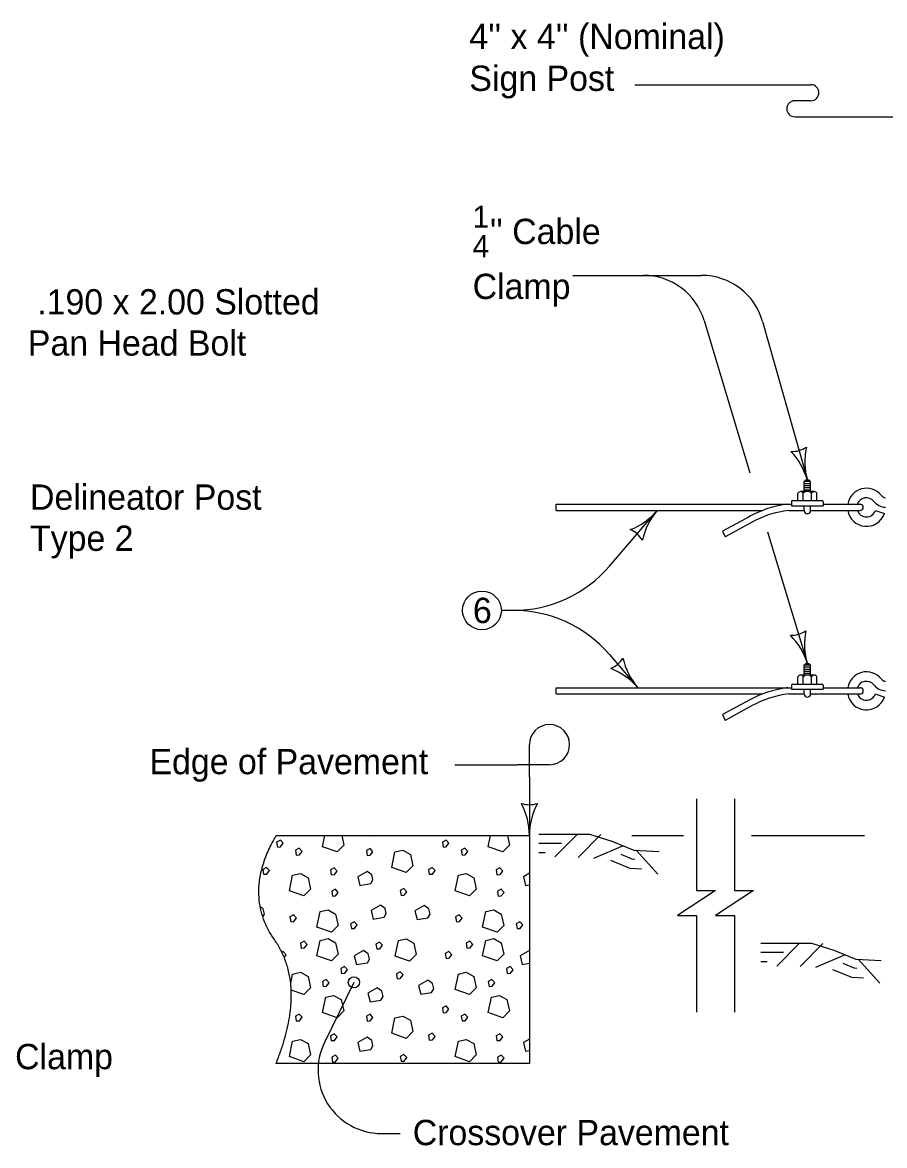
# Model space of a CAD drawing. Extents: x 228 to 3572, y -1307 to 1277.
# Drawn here: x 858 to 1403, y -886 to -176 of the extents above; entities that cross this region are included whole.
import ezdxf

# ---------------------------------------------------------------- set-up
doc = ezdxf.new("R2010")
doc.units = 0
for name, color, linetype in [('dsnStdDimension', 7, 'Continuous'), ('Level 2', 7, 'Continuous'), ('Level 3', 7, 'Continuous')]:
    doc.layers.add(name, color=color, linetype=linetype)

msp = doc.modelspace()

# ---------------------------------------------------------------- linework, layer by layer
at = {"layer": 'dsnStdDimension'}
for p, q in [((1245.31, -215.67), (1356.53, -215.67)), ((1356.53, -225.83), (1346.37, -225.83)), ((1346.37, -235.99), (1428.56, -235.99)), ((1206.22, -336.19), (1287.48, -336.19)), ((1289.05, -364.67), (1318.02, -460.97)), ((1325.97, -365.32), (1354.34, -465.71)), ((1229.26, -520.02), (1259.45, -484.8)), ((1329.22, -498.21), (1354.34, -581.71)), ((1229.26, -575.88), (1247.19, -596.8)), ((1178.7, -653.09), (1178.7, -632.77)), ((1131.52, -645.47), (1171.08, -645.47)), ((1191.4, -645.47), (1171.08, -645.47)), ((1178.7, -653.09), (1178.7, -690.3)), ((1067.85, -783.05), (1049.27, -821.01)), ((1085.2, -878.59), (1096.97, -878.59))]:
    msp.add_line(p, q, dxfattribs=at)
msp.add_circle((1067.85, -783.05), 3.56, dxfattribs=at)
for centre, radius, start, end in [((1356.53, -220.75), 5.08, 270, 90), ((1346.37, -230.91), 5.08, 90, 270), ((1250.74, -376.19), 40, 16.74258, 90), ((1287.48, -376.19), 40, 15.77718, 90), ((1344.49, -430.86), 16.68, 268.04366, 303.51036), ((1395.89, -453.97), 43.18, 167.70452, 195.77701), ((1312.78, -477.45), 43.18, 15.77701, 43.8495), ((1226.67, -456.7), 43.18, 291.32247, 319.39496), ((1292.24, -512.9), 43.18, 139.39496, 167.46744), ((1235.89, -512.29), 16.68, 31.6616, 67.12831), ((1168.52, -467.96), 80, 270, 319.39431), ((1168.52, -627.96), 80, 40.60903, 90), ((1343.91, -547.04), 16.68, 269.00857, 304.47527), ((1312.99, -594.14), 43.18, 16.74192, 44.81441), ((1395.68, -569.27), 43.18, 168.66943, 196.74192), ((1223.62, -569.31), 16.68, 292.86794, 328.33464), ((1279.97, -568.7), 43.18, 192.52881, 220.60129), ((1214.4, -624.9), 43.18, 40.60129, 68.67378), ((1191.4, -632.77), 12.7, 270, 180), ((1178.7, -654.09), 16.68, 252.26665, 287.73335), ((1135.52, -690.3), 43.18, 0, 28.07249), ((1221.88, -690.3), 43.18, 151.92751, 180), ((1085.2, -838.59), 40, 153.92317, 270)]:
    msp.add_arc(centre, radius, start, end, dxfattribs=at)
at = {"layer": 'Level 2'}
for p, q in [((1352.34, -466.54), (1353.17, -465.71)), ((1352.34, -472.86), (1352.34, -466.54)), ((1356, -466.54), (1352.67, -466.54)), ((1356, -467.87), (1352.67, -467.87)), ((1355.5, -465.71), (1353.17, -465.71)), ((1356.34, -466.54), (1355.5, -465.71)), ((1356.34, -472.86), (1356.34, -466.54)), ((1348.34, -478.52), (1348.34, -473.86)), ((1351.67, -472.86), (1350, -472.86)), ((1357, -472.86), (1351.67, -472.86)), ((1351.67, -478.52), (1351.67, -473.86)), ((1356, -469.21), (1352.67, -469.21)), ((1356, -470.54), (1352.67, -470.54)), ((1356, -471.87), (1352.67, -471.87)), ((1358.67, -472.86), (1357, -472.86)), ((1357, -478.52), (1357, -473.86)), ((1360.34, -478.52), (1360.34, -473.86)), ((1195.61, -480.8), (1344.34, -480.8)), ((1195.61, -484.8), (1195.61, -480.8)), ((1344.34, -479.32), (1344.34, -481.8)), ((1344.34, -481.8), (1364.34, -481.8)), ((1345.14, -478.52), (1363.54, -478.52)), ((1352.34, -484.8), (1352.34, -481.8)), ((1356.34, -484.8), (1356.34, -481.8)), ((1364.34, -479.32), (1364.34, -481.8)), ((1364.34, -480.8), (1387.61, -480.8)), ((1195.61, -484.8), (1325.97, -484.8)), ((1317.88, -488.51), (1300.69, -497.81)), ((1342.58, -484.8), (1352.34, -484.8)), ((1356.34, -484.8), (1387.61, -484.8)), ((1397.27, -484.8), (1402.93, -486.79)), ((1319.5, -492.15), (1302.43, -501.49)), ((1300.69, -497.81), (1302.43, -501.49)), ((1168.52, -547.96), (1160.98, -547.96)), ((1352.34, -582.54), (1353.17, -581.71)), ((1355.5, -581.71), (1353.17, -581.71)), ((1356.34, -582.54), (1355.5, -581.71)), ((1351.67, -588.86), (1350, -588.86)), ((1357, -588.86), (1351.67, -588.86)), ((1352.34, -588.86), (1352.34, -582.54)), ((1356, -582.54), (1352.67, -582.54)), ((1356, -583.87), (1352.67, -583.87)), ((1356, -585.21), (1352.67, -585.21)), ((1356, -586.54), (1352.67, -586.54)), ((1356, -587.87), (1352.67, -587.87)), ((1356.34, -588.86), (1356.34, -582.54)), ((1358.67, -588.86), (1357, -588.86)), ((1344.34, -595.32), (1344.34, -597.8)), ((1345.14, -594.52), (1363.54, -594.52)), ((1348.34, -594.52), (1348.34, -589.86)), ((1351.67, -594.52), (1351.67, -589.86)), ((1357, -594.52), (1357, -589.86)), ((1360.34, -594.52), (1360.34, -589.86)), ((1364.34, -595.32), (1364.34, -597.8)), ((1195.61, -596.8), (1344.34, -596.8)), ((1195.61, -600.8), (1195.61, -596.8)), ((1195.61, -600.8), (1325.97, -600.8)), ((1342.58, -600.8), (1352.34, -600.8)), ((1344.34, -597.8), (1364.34, -597.8)), ((1352.34, -600.8), (1352.34, -597.8)), ((1356.34, -600.8), (1356.34, -597.8)), ((1356.34, -600.8), (1387.61, -600.8)), ((1364.34, -596.8), (1387.61, -596.8)), ((1397.27, -600.8), (1402.93, -602.79)), ((1317.88, -604.51), (1300.69, -613.81)), ((1319.5, -608.15), (1302.43, -617.49)), ((1300.69, -613.81), (1302.43, -617.49)), ((1018.7, -690.3), (1178.7, -690.3)), ((1178.7, -690.3), (1178.7, -834.3)), ((1209.09, -689.45), (1194.73, -703.82)), ((1223.83, -689.68), (1209.46, -704.05)), ((1243.43, -690.3), (1275.96, -690.3)), ((1319.05, -690.3), (1390.43, -690.3)), ((1237.99, -696.75), (1219.28, -704.68)), ((1246.23, -699.54), (1259.75, -714.72)), ((1349.34, -758.36), (1334.97, -772.73)), ((1364.07, -758.59), (1349.7, -772.96)), ((1378.23, -765.66), (1359.52, -773.59)), ((1386.48, -768.46), (1399.99, -783.63)), ((1178.7, -834.3), (1018.7, -834.3))]:
    msp.add_line(p, q, dxfattribs=at)
for points in [[(1284.21, -666.96), (1284.21, -724.9), (1296.21, -724.9), (1272.21, -740.9), (1284.21, -740.9), (1284.21, -801.85)], [(1308.21, -666.96), (1308.21, -724.9), (1320.21, -724.9), (1296.21, -740.9), (1308.21, -740.9), (1308.21, -801.85)], [(1060.12, -690.3), (1061.42, -696.26), (1057.22, -700.61), (1048.06, -697.35), (1049.51, -690.3)], [(1077.98, -690.3), (1078.04, -690.52), (1079.4, -690.3)], [(1164.79, -690.3), (1166.09, -696.26), (1161.89, -700.61), (1152.73, -697.35), (1154.18, -690.3)], [(1184.7, -689.45), (1200.7, -689.45), (1216.69, -689.45), (1230.78, -693.83), (1244.69, -699.45), (1260.6, -700.38)], [(1184.7, -695.01), (1198.94, -695.01)], [(1184.7, -700.9), (1188.56, -700.9)], [(1236.38, -702.12), (1243.44, -704.98), (1245.39, -705.09)], [(1229.94, -705.93), (1242.12, -710.86), (1249.57, -711.29)], [(1178.7, -714.13), (1174.94, -716.3)], [(1174.94, -716.3), (1176.34, -721.74), (1178.7, -721.36)], [(1010.28, -741.58), (1011.28, -739.92), (1010.5, -736.65), (1008.61, -735.27)], [(1324.94, -758.36), (1340.94, -758.36), (1356.94, -758.36), (1371.02, -762.74), (1384.93, -768.37), (1400.85, -769.29)], [(1023.89, -767.21), (1025.1, -765.66), (1023.24, -763.64), (1022.37, -764.11)], [(1178.7, -762.9), (1178.67, -762.87), (1172.77, -766.29)], [(1172.77, -766.29), (1174.16, -771.72), (1178.7, -771)], [(1324.94, -763.92), (1339.18, -763.92)], [(1324.94, -769.81), (1328.81, -769.81)], [(1376.62, -771.03), (1383.69, -773.89), (1385.63, -774)], [(1376.62, -771.03), (1383.69, -773.89), (1385.63, -774)], [(1027.93, -783.64), (1029.14, -777.78)], [(1029.14, -777.78), (1034.11, -776.69), (1038.93, -779.34), (1040.48, -786.48), (1036.29, -790.83), (1028.25, -787.97)], [(1370.19, -774.85), (1382.37, -779.77), (1389.81, -780.2)], [(1370.19, -774.85), (1382.37, -779.77), (1389.81, -780.2)], [(1178.7, -818.95), (1174.94, -821.13)], [(1174.94, -821.13), (1176.34, -826.56), (1178.7, -826.19)]]:
    msp.add_lwpolyline(points, dxfattribs=at)
for points in [[(1019.04, -694.4), (1019.51, -697.51), (1021.53, -697.35), (1023.24, -695.17), (1021.37, -693.16)], [(1123.71, -694.4), (1124.18, -697.51), (1126.2, -697.35), (1127.91, -695.17), (1126.04, -693.16)], [(1031.01, -699.52), (1031.47, -702.63), (1033.49, -702.48), (1035.2, -700.3), (1033.34, -698.28)], [(1075.71, -699.68), (1076.18, -702.79), (1078.19, -702.63), (1079.9, -700.46), (1078.04, -698.44)], [(1093.73, -700.61), (1098.7, -699.52), (1103.52, -702.17), (1105.07, -709.31), (1100.88, -713.66), (1091.71, -710.4)], [(1135.67, -699.52), (1136.14, -702.63), (1138.16, -702.48), (1139.87, -700.3), (1138, -698.28)], [(1010.35, -711.64), (1010.81, -714.75), (1012.83, -714.59), (1014.54, -712.42), (1012.68, -710.4)], [(1029.14, -715.37), (1034.11, -714.28), (1038.93, -716.92), (1040.48, -724.07), (1036.29, -728.42), (1027.12, -725.16)], [(1053.03, -711.95), (1053.49, -715.06), (1055.51, -714.9), (1057.22, -712.73), (1055.36, -710.71)], [(1070.27, -716.3), (1071.67, -721.74), (1078.51, -720.65), (1079.9, -718.32), (1079.13, -715.06), (1076.18, -712.89)], [(1115.01, -711.64), (1115.48, -714.75), (1117.5, -714.59), (1119.21, -712.42), (1117.34, -710.4)], [(1133.81, -715.37), (1138.78, -714.28), (1143.6, -716.92), (1145.15, -724.07), (1140.96, -728.42), (1131.79, -725.16)], [(1157.7, -711.95), (1158.16, -715.06), (1160.18, -714.9), (1161.89, -712.73), (1160.03, -710.71)], [(1097.15, -725), (1097.61, -728.11), (1099.63, -727.95), (1101.34, -725.78), (1099.48, -723.76)], [(1053.8, -725.47), (1054.27, -728.58), (1056.29, -728.42), (1058, -726.24), (1056.13, -724.23)], [(1158.47, -725.47), (1158.94, -728.58), (1160.96, -728.42), (1162.67, -726.24), (1160.8, -724.23)], [(1046.5, -738.36), (1051.48, -737.28), (1056.29, -739.92), (1057.84, -747.06), (1053.65, -751.41), (1044.48, -748.15)], [(1078.66, -737.59), (1080.06, -743.02), (1086.9, -741.94), (1088.29, -739.61), (1087.52, -736.34), (1084.56, -734.17)], [(1106.31, -737.9), (1107.71, -743.33), (1114.55, -742.25), (1115.95, -739.92), (1115.17, -736.65), (1112.22, -734.48)], [(1151.17, -738.36), (1156.14, -737.28), (1160.96, -739.92), (1162.51, -747.06), (1158.32, -751.41), (1149.15, -748.15)], [(1027.43, -741.62), (1027.9, -744.73), (1029.92, -744.58), (1031.63, -742.4), (1029.76, -740.38)], [(1065.77, -745.97), (1066.23, -749.08), (1068.25, -748.93), (1069.96, -746.75), (1068.1, -744.73)], [(1132.1, -741.62), (1132.57, -744.73), (1134.59, -744.58), (1136.3, -742.4), (1134.43, -740.38)], [(1170.44, -745.97), (1170.9, -749.08), (1172.92, -748.93), (1174.63, -746.75), (1172.76, -744.73)], [(1034.11, -758.36), (1034.58, -761.47), (1036.6, -761.31), (1038.31, -759.14), (1036.44, -757.12)], [(1046.5, -756.5), (1051.48, -755.41), (1056.29, -758.05), (1057.85, -765.2), (1053.65, -769.55), (1044.49, -766.29)], [(1081.77, -758.83), (1082.23, -761.94), (1084.25, -761.78), (1085.96, -759.61), (1084.1, -757.59)], [(1095.91, -756.65), (1100.88, -755.57), (1105.69, -758.21), (1107.25, -765.35), (1103.05, -769.7), (1093.89, -766.44)], [(1138.78, -758.36), (1139.25, -761.47), (1141.27, -761.31), (1142.98, -759.14), (1141.11, -757.12)], [(1151.17, -756.5), (1156.14, -755.41), (1160.96, -758.05), (1162.51, -765.2), (1158.32, -769.55), (1149.15, -766.29)], [(1068.1, -766.29), (1069.5, -771.72), (1076.33, -770.64), (1077.73, -768.31), (1076.95, -765.04), (1074, -762.87)], [(1125.58, -764.89), (1126.04, -767.99), (1128.06, -767.84), (1129.77, -765.66), (1127.91, -763.64)], [(1059.55, -774.36), (1060.02, -777.47), (1062.04, -777.32), (1063.75, -775.14), (1061.88, -773.12)], [(1164.22, -774.36), (1164.69, -777.47), (1166.71, -777.32), (1168.42, -775.14), (1166.55, -773.12)], [(1094.66, -777.63), (1095.13, -780.73), (1097.15, -780.58), (1098.86, -778.4), (1096.99, -776.38)], [(1133.81, -777.78), (1138.78, -776.69), (1143.6, -779.34), (1145.15, -786.48), (1140.96, -790.83), (1131.79, -787.57)], [(1048.06, -782.6), (1048.52, -785.7), (1050.54, -785.55), (1052.25, -783.37), (1050.39, -781.35)], [(1076.64, -789.9), (1078.04, -795.34), (1084.88, -794.25), (1086.27, -791.92), (1085.5, -788.66), (1082.55, -786.48)], [(1108.64, -785.08), (1110.04, -790.52), (1116.88, -789.43), (1118.28, -787.1), (1117.5, -783.84), (1114.55, -781.67)], [(1152.73, -782.6), (1153.19, -785.7), (1155.21, -785.55), (1156.92, -783.37), (1155.06, -781.35)], [(1050.08, -792.38), (1055.05, -791.3), (1059.86, -793.94), (1061.42, -801.08), (1057.22, -805.43), (1048.06, -802.17)], [(1154.75, -792.38), (1159.72, -791.3), (1164.53, -793.94), (1166.09, -801.08), (1161.89, -805.43), (1152.73, -802.17)], [(1123.71, -799.22), (1124.18, -802.33), (1126.2, -802.17), (1127.91, -800), (1126.04, -797.98)], [(1031.01, -804.35), (1031.47, -807.45), (1033.49, -807.3), (1035.2, -805.12), (1033.34, -803.1)], [(1075.71, -804.5), (1076.18, -807.61), (1078.19, -807.45), (1079.9, -805.28), (1078.04, -803.26)], [(1093.73, -805.43), (1098.7, -804.35), (1103.52, -806.99), (1105.07, -814.13), (1100.88, -818.48), (1091.71, -815.22)], [(1135.67, -804.35), (1136.14, -807.45), (1138.16, -807.3), (1139.87, -805.12), (1138, -803.1)], [(1053.03, -816.77), (1053.49, -819.88), (1055.51, -819.73), (1057.22, -817.55), (1055.36, -815.53)], [(1115.01, -816.46), (1115.48, -819.57), (1117.5, -819.42), (1119.21, -817.24), (1117.34, -815.22)], [(1157.7, -816.77), (1158.16, -819.88), (1160.18, -819.73), (1161.89, -817.55), (1160.03, -815.53)], [(1029.14, -820.19), (1034.11, -819.11), (1038.93, -821.75), (1040.48, -828.89), (1036.29, -833.24), (1027.12, -829.98)], [(1070.27, -821.13), (1071.67, -826.56), (1078.51, -825.48), (1079.9, -823.14), (1079.13, -819.88), (1076.18, -817.71)], [(1133.81, -820.19), (1138.78, -819.11), (1143.6, -821.75), (1145.15, -828.89), (1140.96, -833.24), (1131.79, -829.98)], [(1053.8, -830.29), (1054.27, -833.4), (1056.29, -833.24), (1058, -831.07), (1056.13, -829.05)], [(1097.15, -829.82), (1097.61, -832.93), (1099.63, -832.78), (1101.34, -830.6), (1099.48, -828.58)], [(1158.47, -830.29), (1158.94, -833.4), (1160.96, -833.24), (1162.67, -831.07), (1160.8, -829.05)]]:
    msp.add_lwpolyline(points, close=True, dxfattribs=at)
msp.add_circle((1148.73, -547.96), 12.25, dxfattribs=at)
for centre, radius, start, end in [((1350, -474.75), 1.89, 28.07249, 151.92751), ((1354.34, -476.91), 4.05, 48.88791, 131.11209), ((1358.67, -474.75), 1.89, 28.07249, 151.92751), ((1391.61, -482.8), 12, 39.12902, 170.40593), ((1404.12, -472.78), 4.02, 217.44554, 262.43895), ((1350.35, -548.55), 68.26, 96.97565, 119.10588), ((1345.14, -479.32), 0.8, 90, 180), ((1363.54, -479.32), 0.8, 0, 90), ((1391.61, -482.8), 6, 41.04041, 160.52878), ((1387.61, -482.8), 2, 270, 90), ((1404.12, -472.78), 10.04, 217.30891, 267.0982), ((1350.35, -548.55), 64.29, 96.97565, 119.10588), ((1354.34, -484.8), 2, 180, 0), ((1391.61, -482.8), 12, 189.59407, 340.56372), ((1391.61, -482.8), 6, 199.47122, 340.56498), ((1350, -590.75), 1.89, 28.07249, 151.92751), ((1354.34, -592.91), 4.05, 48.88791, 131.11209), ((1358.67, -590.75), 1.89, 28.07249, 151.92751), ((1391.61, -598.8), 12, 39.12902, 170.40593), ((1345.14, -595.32), 0.8, 90, 180), ((1363.54, -595.32), 0.8, 0, 90), ((1391.61, -598.8), 6, 41.04041, 160.52878), ((1404.12, -588.78), 10.04, 217.30891, 267.0982), ((1404.12, -588.78), 4.02, 217.44554, 262.43895), ((1350.35, -664.55), 68.26, 96.97565, 119.10588), ((1350.35, -664.55), 64.29, 96.97565, 119.10588), ((1354.34, -600.8), 2, 180, 0), ((1391.61, -598.8), 12, 189.59407, 340.56372), ((1391.61, -598.8), 6, 199.47122, 340.56498), ((1387.61, -598.8), 2, 270, 90)]:
    msp.add_arc(centre, radius, start, end, dxfattribs=at)
msp.add_open_spline([(1018.7, -834.3), (1038.31, -785.62), (997.32, -727.11), (1018.7, -690.3)], degree=2, dxfattribs=at)

# ---------------------------------------------------------------- texts
at = {"layer": 'dsnStdDimension'}
for s, height, p in [("4'' x 4'' (Nominal)", 16, (1140.77, -193.2)), ('Sign Post', 16, (1140.77, -219.6)), ('1', 14, (1142.84, -306.09)), ("'' Cable", 16, (1153.72, -316.42)), ('4', 14, (1142.84, -324.76)), ('Clamp', 16, (1142.84, -351.16)), (' .190 x 2.00 Slotted ', 16, (861.85, -360.93)), ('Pan Head Bolt', 16, (861.85, -386.93)), ('Delineator Post', 16, (863.23, -484.34)), ('Type 2', 16, (863.23, -510.34)), ('Edge of Pavement', 16, (938.68, -651.51)), ("'' Cable Clamp", 16, (777.84, -837.96)), ('Crossover Pavement', 16, (1105, -885.97))]:
    msp.add_text(s, height=height, dxfattribs=at).set_placement(p)
at = {"layer": 'Level 3'}
msp.add_text('6', height=16, dxfattribs=at).set_placement((1143.02, -555.96))

doc.saveas('drawing.dxf')
